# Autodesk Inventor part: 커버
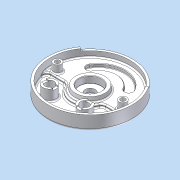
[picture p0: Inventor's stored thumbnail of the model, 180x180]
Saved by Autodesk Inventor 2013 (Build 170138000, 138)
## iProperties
Company: 한국ATC센터
Created: 2015-04
Part Number: 커버
Document SubType Name: Modeling
Designer: KYOUNG IL JANG
Density: 1 g/cm^3
Material: 일반
Mass: 394.015 g
Surface Area: 1019.6 cm^2
Volume: 394.015 cm^3
Author: KYOUNG IL JANG
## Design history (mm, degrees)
sketch "스케치1"
  geometry: L1 (-59, -19)-(-59, 19); L2 (59, 19)-(59, -19); L3 (-41, 19)-(-41, -19); L4 (41, -19)-(41, 19); L5 (38.527, 33.023)-(55.442, 39.179); L6 (-38.527, 33.023)-(-55.442, 39.179); C1 r 90 at (0, 0); C2 r 95 at (0, 0); A1 r 59 centre (0, 19) between (59, 19) and (-59, 19); A2 r 59 centre (0, -19) between (-59, -19) and (59, -19); A3 r 41 centre (0, -19) between (-41, -19) and (41, -19); A4 r 41 centre (0, 19) between (41, 19) and (-41, 19); 2 further points
  constraints: 12 end point, 12 point on circle, 6 centre point, 4 tangent, 2 parallel, 2 point on line, 1 coincident, 1 horizontal alignment, 1 midpoint, 1 vertical, 1 vertical alignment, 3 other
  dimensions: "d2" = 180 diameter of C1; "d3" = 156 dimension on A2 A1; "d4" = 118 distance between parallel lines of L2 L1; "d5" = 18 distance between parallel lines of L2 L4; "d8" = 190 diameter of C2; "d120" = 140 deg angle of L6 L5; "d121" = 110 deg dimension on A1.centre point (0, 0) L5.end
extrude "돌출1" new body sketch "스케치1" distance "d6" = 14; taper "d7" = 0 deg
extrude "돌출2" join sketch "스케치1" distance "d9" = 13; taper "d10" = 0 deg
extrude "돌출3" cut sketch "스케치1" distance "d11" = 7; taper "d12" = 0 deg
sketch "스케치2"
  geometry: C1 r 11.5 at (0, 0); 1 further point
  constraints: 1 centre point, 1 coincident
  dimensions: "d13" = 23 diameter of C1
extrude "돌출4" cut sketch "스케치2" stored distance "d14" = 7; taper "d15" = 0 deg
fillet "모깎기1"
fillet "모깎기2"
sketch "스케치3"
  geometry: L1 (-73.724, 51.622)-(-77.819, 54.49); L2 (73.724, 51.622)-(77.819, 54.49); L3 (0, 0)-(0, -90); A1 r 95 centre (0, 0) between (-77.819, 54.49) and (77.819, 54.49) reference; A2 r 90 centre (0, 0) between (-73.724, 51.622) and (73.724, 51.622) reference; 1 further point
  constraints: 6 end point, 5 point on circle, 1 point on line, 1 vertical, 1 other
  dimensions: "d16" = 250 deg dimension on L2 L1
extrude "돌출5" join sketch "스케치3" distance "d17" = 5; taper "d18" = 0 deg
hole "구멍1" diameter "d21" = 50; stored, may be unused: countersink angle "d25" = 90 deg, drill point angle "d27" = 0 deg; dims "d19" = 10, "d20" = 10, "d22" = 6, "d23" = 4, "d24" = 2, "d26" = 5
fillet "모깎기3" dims "d28" = 0.3
fillet "모깎기5" dims "d30" = 3
sketch "스케치4"
  geometry: C1 r 35 at (0, 0); C2 r 25 at (0, 0); 1 further point
  constraints: 2 centre point, 1 coincident
  dimensions: "d32" = 70 diameter of C1 (derived); "d36" = 10 radial gap between concentric circles of C1 C2
extrude "돌출6" join sketch "스케치4" distance "d33" = 10; taper "d34" = 0 deg
feature "면 기울기2" dims angle "d37" = 10 deg
chamfer "모따기1" distance "d39" = 1; stored, may be unused: second distance "d40" = 2, angle "d41" = 45 deg
fillet "모깎기7" dims "d42" = 5
sketch "스케치5"
  geometry: L1 (-40.249, -12)-(-89.196, -12); L2 (40.249, -12)-(89.196, -12); A1 r 90 centre (0, 0) between (-89.196, -12) and (89.196, -12) reference; A2 r 42 centre (0, 0) between (-40.249, -12) and (40.249, -12); 1 further point
  constraints: 4 end point, 4 point on circle, 1 centre point, 1 collinear, 1 horizontal, 1 point on line
  dimensions: "d43" = 48 radial gap between concentric circles of A1 A2; "d44" = 12 distance from line of point (0, 0) L1
extrude "돌출7" cut sketch "스케치5" stored distance "d45" = 10; taper "d46" = 0 deg
fillet "모깎기8" dims "d47" = 10
chamfer "모따기2" distance "d49" = 1; stored, may be unused: second distance "d50" = 2, angle "d51" = 45 deg
sketch "스케치7"
  geometry: L1 (36.062, 36.062)-(50.912, 50.912); L2 (-36.062, 36.062)-(-50.912, 50.912); A1 r 72 centre (0, 0) between (50.912, 50.912) and (-50.912, 50.912); A2 r 51 centre (0, 0) between (36.062, 36.062) and (-36.062, 36.062); 1 further point
  constraints: 8 point on circle, 4 end point, 2 centre point, 2 point on line, 1 coincident, 1 horizontal alignment
  dimensions: "d54" = 72 radius of A1; "d55" = 21 radial gap between concentric circles of A1 A2; "d56" = 90 deg angle of L2 L1
extrude "돌출8" join sketch "스케치7" distance "d57" = 5; taper "d58" = 0 deg
fillet "모깎기10" dims "d59" = 5
fillet "모깎기11" dims "d60" = 5
fillet "모깎기12" dims "d61" = 3
sketch "스케치6"
  geometry: C1 r 68 at (0, 0); 1 further point
  constraints: 1 centre point, 1 other
  dimensions: "d119" = 136 diameter of C1
feature "엠보싱1" sketch "스케치6" dims "d62" = 0.5, "d63" = 0
sketch "스케치8"
  geometry: C1 r 9 at (74, 0); C2 r 9 at (-74, 0); A1 r 74 centre (0, 0) between (74, 0) and (-74, 0); 1 further point
  constraints: 3 centre point, 2 horizontal alignment, 2 point on circle, 1 coincident, 1 equal radius
  dimensions: "d64" = 18 diameter of C1; "d65" = 148 diameter of A1
extrude "돌출9" join sketch "스케치8" stored distance "d66" = 5; taper "d67" = 0 deg
sketch "스케치11"
  geometry: C1 r 15 at (40, -52); C2 r 15 at (-40, -52); 1 further point
  constraints: 2 centre point, 1 equal radius, 1 horizontal alignment
  dimensions: "d83" = 52 vertical distance of point (0, 0) C1.centre; "d84" = 80 distance of C2.centre C1.centre; "d85" = 40 horizontal distance of point (0, 0) C1.centre (= 0.5 x d84); "d86" = 30 diameter of C1
extrude "돌출10" join sketch "스케치11" stored distance "d87" = 5; taper "d88" = 0 deg
node "구멍3"
node "구멍5"
hole "구멍6" diameter "d93" = 20; stored, may be unused: countersink angle "d97" = 90 deg, drill point angle "d99" = 118 deg; dims "d91" = 10, "d92" = 10, "d94" = 6, "d95" = 4, "d96" = 2, "d98" = 8
hole "구멍7" diameter "d102" = 20; stored, may be unused: countersink angle "d106" = 90 deg, drill point angle "d108" = 118 deg; dims "d100" = 10, "d101" = 10, "d103" = 6, "d104" = 4, "d105" = 2, "d107" = 8
sketch "스케치13"
  geometry: L1 (6, -13.748)-(6, -8); L2 (6, 8)-(6, 13.748); L3 (-6, -13.748)-(-6, -8); L4 (-6, 8)-(-6, 13.748); L5 (-66.252, -6)-(-72, -6); L6 (-88, -6)-(-93.748, -6); L7 (-66.252, 6)-(-72, 6); L8 (-88, 6)-(-93.748, 6); A1 r 15 centre (0, 0) between (6, -13.748) and (6, 13.748) reference; A2 r 10 centre (0, 0) between (6, -8) and (6, 8) reference; A3 r 15 centre (-80, 0) between (-66.252, -6) and (-93.748, -6) reference; A4 r 10 centre (-80, 0) between (-72, -6) and (-88, -6) reference; 1 further point
  constraints: 16 end point, 16 point on circle, 4 equal length, 3 collinear, 2 point on line, 1 perpendicular, 1 vertical
  dimensions: "d109" = 12 distance between parallel lines of L3 L1; "d110" = 6 distance from line of A1.centre L1 (= 0.5 x d109); "d111" = 12 distance between parallel lines of L7 L5; "d112" = 6 distance from line of A3.centre L5 (= 0.5 x d111)
extrude "돌출12" cut sketch "스케치13" distance "d113" = 3; taper "d114" = 0 deg
fillet "모깎기13" dims "d115" = 3
fillet "모깎기14" dims "d116" = 1
node "솔리드1"
sketch "스케치9"
  geometry: 1 further point
hole "구멍2" sketch "스케치9" diameter "d68" = 11; stored, may be unused: countersink angle "d72" = 90 deg, drill point angle "d74" = 0 deg; dims "d69" = 6, "d70" = 18, "d71" = 11, "d73" = 8
sketch "스케치10"
  geometry: 1 further point
hole "구멍4" sketch "스케치10" diameter "d75" = 11; stored, may be unused: countersink angle "d79" = 90 deg, drill point angle "d81" = 0 deg; dims "d76" = 6, "d77" = 18, "d78" = 11, "d80" = 8
